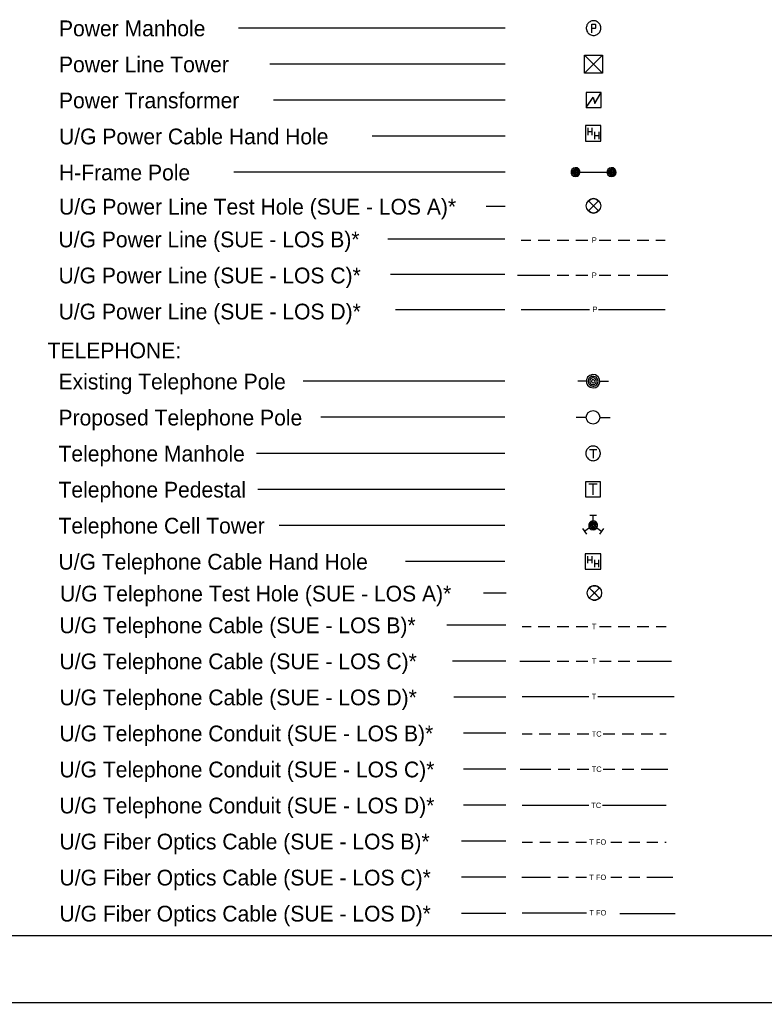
# Model space of a CAD drawing. Extents: x 0 to 3, y 0 to 1.83.
# Drawn here: x 1.443 to 2.138, y 0 to 0.917 of the extents above; entities that cross this region are included whole.
import ezdxf

# ---------------------------------------------------------------- set-up
doc = ezdxf.new("R2010")
doc.units = 0
for name, color, linetype in [('Prop DSN Text', 7, 'Continuous'), ('Scratch_Level_3', 7, 'Continuous'), ('Sheet_Plan', 7, 'Continuous'), ('Sheet_Symbology', 7, 'Continuous'), ('z - Construction', 7, 'Continuous')]:
    doc.layers.add(name, color=color, linetype=linetype)

msp = doc.modelspace()

# ---------------------------------------------------------------- linework, layer by layer
at = {"layer": 'Prop DSN Text'}
for points in [[(1.98436, 0.38682), (1.97486, 0.37732), (1.97961, 0.38207), (1.97486, 0.38682), (1.98436, 0.37732)], [(1.97486, 0.38682), (1.97961, 0.38207), (1.98436, 0.38682)], [(1.98436, 0.37732), (1.97961, 0.38207), (1.97486, 0.37732)]]:
    msp.add_lwpolyline(points, dxfattribs=at)
msp.add_circle((1.97961, 0.38207), 0.00672, dxfattribs=at)
for start, end in [(45, 135), (225, 315)]:
    msp.add_arc((1.97961, 0.38207), 0.00672, start, end, dxfattribs=at)
at = {"layer": 'Scratch_Level_3'}
for points in [[(1.98357, 0.74811), (1.97406, 0.7386), (1.97881, 0.74336), (1.97406, 0.74811), (1.98357, 0.7386)], [(1.97406, 0.74811), (1.97881, 0.74336), (1.98357, 0.74811)], [(1.98357, 0.7386), (1.97881, 0.74336), (1.97406, 0.7386)]]:
    msp.add_lwpolyline(points, dxfattribs=at)
msp.add_circle((1.97881, 0.74336), 0.00672, dxfattribs=at)
for start, end in [(45, 135), (225, 315)]:
    msp.add_arc((1.97881, 0.74336), 0.00672, start, end, dxfattribs=at)
at = {"layer": 'Sheet_Plan'}
msp.add_line((0.0625, 0.0625), (2.77079, 0.0625), dxfattribs=at)
at = {"layer": 'Sheet_Symbology'}
for p, q in [((1.89643, 0.90927), (1.6473, 0.90927)), ((1.98022, 0.90894), (1.97716, 0.90894)), ((1.98076, 0.91238), (1.98076, 0.90949)), ((1.98729, 0.88408), (1.9705, 0.86728)), ((1.98729, 0.86728), (1.9705, 0.88408)), ((1.89643, 0.87564), (1.67671, 0.87564)), ((1.89643, 0.84201), (1.68012, 0.84201)), ((1.89643, 0.80837), (1.77218, 0.80837)), ((1.97335, 0.8161), (1.97335, 0.80932)), ((1.97335, 0.81264), (1.97722, 0.81264)), ((1.97722, 0.8161), (1.97722, 0.80932)), ((1.97982, 0.8124), (1.97982, 0.80563)), ((1.97982, 0.80895), (1.98369, 0.80895)), ((1.98369, 0.8124), (1.98369, 0.80563)), ((1.89643, 0.77474), (1.64304, 0.77474)), ((1.96204, 0.77474), (1.99567, 0.77474)), ((1.89643, 0.74283), (1.87855, 0.74283)), ((1.89598, 0.71229), (1.78681, 0.71229)), ((1.91113, 0.71146), (1.92038, 0.71146)), ((1.92711, 0.71146), (1.93804, 0.71146)), ((1.94476, 0.71146), (1.95569, 0.71146)), ((1.96242, 0.71146), (1.97335, 0.71146)), ((1.98411, 0.71146), (1.99504, 0.71146)), ((2.00177, 0.71146), (2.0127, 0.71146)), ((2.01942, 0.71146), (2.03035, 0.71146)), ((2.03708, 0.71146), (2.04566, 0.71146)), ((1.89598, 0.6793), (1.7894, 0.6793)), ((1.90773, 0.67866), (1.93804, 0.67866)), ((1.94476, 0.67866), (1.95569, 0.67866)), ((1.96242, 0.67866), (1.97335, 0.67866)), ((1.98411, 0.67866), (1.99504, 0.67866)), ((2.00177, 0.67866), (2.0127, 0.67866)), ((2.01942, 0.67866), (2.04806, 0.67866)), ((1.89598, 0.64631), (1.79392, 0.64631)), ((1.91113, 0.64678), (1.97518, 0.64678)), ((1.98358, 0.64678), (2.04566, 0.64678)), ((1.89598, 0.57963), (1.70783, 0.57963)), ((1.97218, 0.57963), (1.96412, 0.57963)), ((1.9846, 0.57963), (1.99267, 0.57963)), ((1.89598, 0.546), (1.72435, 0.546)), ((1.97215, 0.54598), (1.96269, 0.54598)), ((1.98476, 0.54598), (1.99422, 0.54598)), ((1.98189, 0.51554), (1.97495, 0.51554)), ((1.97839, 0.51554), (1.97839, 0.50789)), ((1.89598, 0.51237), (1.66415, 0.51237)), ((1.89598, 0.47874), (1.66533, 0.47874)), ((1.97446, 0.48381), (1.98233, 0.48381)), ((1.97839, 0.47367), (1.97839, 0.48381)), ((1.97524, 0.45462), (1.98155, 0.45462)), ((1.97839, 0.44925), (1.97839, 0.45462)), ((1.89598, 0.44511), (1.6854, 0.44511)), ((1.97242, 0.43707), (1.9688, 0.44224)), ((1.97502, 0.44274), (1.97061, 0.43965)), ((1.98179, 0.44275), (1.98619, 0.43966)), ((1.988, 0.44224), (1.98438, 0.43708)), ((1.97324, 0.41656), (1.97324, 0.40979)), ((1.97324, 0.41311), (1.97711, 0.41311)), ((1.97711, 0.41656), (1.97711, 0.40979)), ((1.97971, 0.41287), (1.97971, 0.4061)), ((1.98358, 0.41287), (1.98358, 0.4061)), ((1.89598, 0.41148), (1.80343, 0.41148)), ((1.97971, 0.40942), (1.98358, 0.40942)), ((1.89735, 0.38175), (1.87607, 0.38175)), ((1.89689, 0.35212), (1.84177, 0.35212)), ((1.91205, 0.35078), (1.9205, 0.35078)), ((1.92723, 0.35078), (1.93816, 0.35078)), ((1.94488, 0.35078), (1.95581, 0.35078)), ((1.96254, 0.35078), (1.97347, 0.35078)), ((1.98423, 0.35078), (1.99516, 0.35078)), ((2.00189, 0.35078), (2.01282, 0.35078)), ((2.01954, 0.35078), (2.03047, 0.35078)), ((2.0372, 0.35078), (2.04657, 0.35078)), ((1.89689, 0.31849), (1.84708, 0.31849)), ((1.90995, 0.31849), (1.93816, 0.31849)), ((1.94488, 0.31849), (1.95581, 0.31849)), ((1.96254, 0.31849), (1.97347, 0.31849)), ((1.98423, 0.31849), (1.99516, 0.31849)), ((2.00189, 0.31849), (2.01282, 0.31849)), ((2.01954, 0.31849), (2.05156, 0.31849)), ((1.89689, 0.28486), (1.84837, 0.28486)), ((1.91205, 0.28545), (1.97448, 0.28545)), ((1.98288, 0.28545), (2.05415, 0.28545)), ((1.89689, 0.25123), (1.85744, 0.25123)), ((1.91205, 0.25051), (1.92144, 0.25051)), ((1.92817, 0.25051), (1.9391, 0.25051)), ((1.94583, 0.25051), (1.95676, 0.25051)), ((1.96348, 0.25051), (1.97441, 0.25051)), ((1.98787, 0.25051), (1.9988, 0.25051)), ((2.00552, 0.25051), (2.01645, 0.25051)), ((2.02318, 0.25051), (2.03411, 0.25051)), ((2.04084, 0.25051), (2.04657, 0.25051)), ((1.89689, 0.21759), (1.85744, 0.21759)), ((1.91045, 0.21759), (1.9391, 0.21759)), ((1.94583, 0.21759), (1.95676, 0.21759)), ((1.96348, 0.21759), (1.97441, 0.21759)), ((1.98787, 0.21759), (1.9988, 0.21759)), ((2.00552, 0.21759), (2.01645, 0.21759)), ((2.02318, 0.21759), (2.04819, 0.21759)), ((1.89689, 0.18396), (1.85744, 0.18396)), ((1.91205, 0.18388), (1.97441, 0.18388)), ((1.98703, 0.18388), (2.04657, 0.18388)), ((1.89689, 0.15033), (1.85549, 0.15033)), ((1.91205, 0.1496), (1.92187, 0.1496)), ((1.92859, 0.1496), (1.93868, 0.1496)), ((1.94541, 0.1496), (1.9555, 0.1496)), ((1.96222, 0.1496), (1.97231, 0.1496)), ((1.99501, 0.1496), (2.0051, 0.1496)), ((2.01183, 0.1496), (2.02192, 0.1496)), ((2.02864, 0.1496), (2.03873, 0.1496)), ((2.04546, 0.1496), (2.04657, 0.1496)), ((1.89689, 0.1167), (1.85549, 0.1167)), ((1.91174, 0.1167), (1.93868, 0.1167)), ((1.94541, 0.1167), (1.9555, 0.1167)), ((1.96222, 0.1167), (1.97231, 0.1167)), ((1.99501, 0.1167), (2.0051, 0.1167)), ((2.01183, 0.1167), (2.02192, 0.1167)), ((2.02864, 0.1167), (2.05271, 0.1167)), ((1.89689, 0.08307), (1.85549, 0.08307)), ((1.91205, 0.08362), (1.97238, 0.08362)), ((2.00348, 0.08298), (2.05498, 0.08298))]:
    msp.add_line(p, q, dxfattribs=at)
for points in [[(1.97885, 0.91609), (1.97798, 0.91604), (1.97716, 0.91588), (1.97634, 0.9156), (1.97558, 0.91522), (1.97487, 0.91478), (1.97421, 0.91424), (1.97361, 0.91358), (1.97312, 0.91293), (1.97268, 0.91216), (1.97241, 0.91134), (1.97219, 0.91052), (1.97208, 0.90971), (1.97208, 0.90883), (1.97219, 0.90801), (1.97241, 0.90714), (1.97268, 0.90637), (1.97312, 0.90561), (1.97361, 0.90495), (1.97421, 0.9043), (1.97487, 0.90375), (1.97558, 0.90332), (1.97634, 0.90293), (1.97716, 0.90266), (1.97803, 0.9025), (1.97885, 0.90244), (1.97973, 0.9025), (1.98054, 0.90266), (1.98137, 0.90293), (1.98213, 0.90332), (1.98284, 0.90375), (1.98349, 0.9043), (1.9841, 0.90495), (1.98459, 0.90561), (1.98503, 0.90637), (1.9853, 0.90719), (1.98552, 0.90801), (1.98562, 0.90883), (1.98562, 0.90971), (1.98552, 0.91052), (1.9853, 0.9114), (1.98503, 0.91216), (1.98459, 0.91293), (1.9841, 0.91358), (1.98349, 0.91424), (1.98284, 0.91478), (1.98213, 0.91522), (1.98137, 0.9156), (1.98054, 0.91588), (1.97967, 0.91604), (1.97885, 0.91609)], [(1.97716, 0.9049), (1.97716, 0.90894), (1.97716, 0.91293), (1.98022, 0.91293)], [(1.98022, 0.91293), (1.98044, 0.91287), (1.9806, 0.91276), (1.98071, 0.9126), (1.98076, 0.91238)], [(1.98076, 0.90949), (1.98071, 0.90927), (1.9806, 0.9091), (1.98044, 0.909), (1.98022, 0.90894)], [(1.98729, 0.86728), (1.9705, 0.86728), (1.9705, 0.88408), (1.98729, 0.88408), (1.98729, 0.86728), (1.9705, 0.86728), (1.9705, 0.88408), (1.98729, 0.88408), (1.98729, 0.86728)], [(1.97184, 0.835), (1.97846, 0.84451), (1.98007, 0.83934), (1.98586, 0.84901)], [(1.97184, 0.835), (1.97852, 0.8449), (1.98002, 0.83895), (1.98586, 0.84901)], [(1.97184, 0.835), (1.98586, 0.835), (1.98586, 0.84901), (1.97184, 0.84901), (1.97184, 0.835)], [(1.97126, 0.80377), (1.98574, 0.80377), (1.98574, 0.81825), (1.97126, 0.81825), (1.97126, 0.80377)], [(1.9651, 0.77474), (1.96502, 0.77549), (1.96477, 0.77615), (1.96435, 0.77673), (1.96386, 0.77722), (1.96328, 0.77756), (1.96253, 0.77772), (1.96187, 0.77781), (1.96113, 0.77764), (1.96046, 0.77739), (1.95997, 0.77698), (1.95947, 0.7764), (1.95914, 0.77582), (1.95897, 0.77507), (1.95897, 0.77441), (1.95914, 0.77367), (1.95947, 0.77309), (1.95997, 0.77251), (1.96046, 0.7721), (1.96113, 0.77185), (1.96187, 0.77168), (1.96253, 0.77176), (1.96328, 0.77193), (1.96386, 0.77226), (1.96435, 0.77276), (1.96477, 0.77334), (1.96502, 0.774), (1.9651, 0.77474)], [(1.9641, 0.77474), (1.96402, 0.77532), (1.96377, 0.7759), (1.96336, 0.77632), (1.96287, 0.77665), (1.96237, 0.77681), (1.96171, 0.77681), (1.96121, 0.77665), (1.96071, 0.77632), (1.9603, 0.7759), (1.96005, 0.77532), (1.95997, 0.77474), (1.96005, 0.77416), (1.9603, 0.77359), (1.96071, 0.77317), (1.96121, 0.77284), (1.96171, 0.77268), (1.96237, 0.77268), (1.96287, 0.77284), (1.96336, 0.77317), (1.96377, 0.77359), (1.96402, 0.77416), (1.9641, 0.77474)], [(1.96303, 0.77474), (1.96295, 0.77516), (1.9627, 0.77549), (1.96237, 0.77565), (1.96195, 0.77574), (1.96154, 0.77557), (1.96121, 0.77532), (1.96104, 0.77491), (1.96104, 0.77458), (1.96121, 0.77416), (1.96154, 0.77391), (1.96195, 0.77375), (1.96237, 0.77383), (1.9627, 0.774), (1.96295, 0.77433), (1.96303, 0.77474)], [(1.99873, 0.77474), (1.99865, 0.77549), (1.9984, 0.77615), (1.99798, 0.77673), (1.99749, 0.77722), (1.99691, 0.77756), (1.99616, 0.77772), (1.9955, 0.77781), (1.99476, 0.77764), (1.9941, 0.77739), (1.9936, 0.77698), (1.9931, 0.7764), (1.99277, 0.77582), (1.9926, 0.77507), (1.9926, 0.77441), (1.99277, 0.77367), (1.9931, 0.77309), (1.9936, 0.77251), (1.9941, 0.7721), (1.99476, 0.77185), (1.9955, 0.77168), (1.99616, 0.77176), (1.99691, 0.77193), (1.99749, 0.77226), (1.99798, 0.77276), (1.9984, 0.77334), (1.99865, 0.774), (1.99873, 0.77474)], [(1.99774, 0.77474), (1.99765, 0.77532), (1.99741, 0.7759), (1.99699, 0.77632), (1.9965, 0.77665), (1.996, 0.77681), (1.99534, 0.77681), (1.99484, 0.77665), (1.99434, 0.77632), (1.99393, 0.7759), (1.99368, 0.77532), (1.9936, 0.77474), (1.99368, 0.77416), (1.99393, 0.77359), (1.99434, 0.77317), (1.99484, 0.77284), (1.99534, 0.77268), (1.996, 0.77268), (1.9965, 0.77284), (1.99699, 0.77317), (1.99741, 0.77359), (1.99765, 0.77416), (1.99774, 0.77474)], [(1.99666, 0.77474), (1.99658, 0.77516), (1.99633, 0.77549), (1.996, 0.77565), (1.99559, 0.77574), (1.99517, 0.77557), (1.99484, 0.77532), (1.99467, 0.77491), (1.99467, 0.77458), (1.99484, 0.77416), (1.99517, 0.77391), (1.99559, 0.77375), (1.996, 0.77383), (1.99633, 0.774), (1.99658, 0.77433), (1.99666, 0.77474)], [(1.98299, 0.57963), (1.98286, 0.58075), (1.98249, 0.58174), (1.98187, 0.58261), (1.98112, 0.58335), (1.98026, 0.58385), (1.97914, 0.5841), (1.97814, 0.58423), (1.97703, 0.58398), (1.97603, 0.5836), (1.97529, 0.58298), (1.97455, 0.58211), (1.97405, 0.58124), (1.9738, 0.58013), (1.9738, 0.57914), (1.97405, 0.57802), (1.97455, 0.57715), (1.97529, 0.57628), (1.97603, 0.57566), (1.97703, 0.57529), (1.97814, 0.57504), (1.97914, 0.57516), (1.98026, 0.57541), (1.98112, 0.57591), (1.98187, 0.57665), (1.98249, 0.57752), (1.98286, 0.57852), (1.98299, 0.57963)], [(1.9815, 0.57963), (1.98137, 0.5805), (1.981, 0.58137), (1.98038, 0.58199), (1.97964, 0.58249), (1.97889, 0.58273), (1.9779, 0.58273), (1.97715, 0.58249), (1.97641, 0.58199), (1.97579, 0.58137), (1.97541, 0.5805), (1.97529, 0.57963), (1.97541, 0.57876), (1.97579, 0.5779), (1.97641, 0.57727), (1.97715, 0.57678), (1.9779, 0.57653), (1.97889, 0.57653), (1.97964, 0.57678), (1.98038, 0.57727), (1.981, 0.5779), (1.98137, 0.57876), (1.9815, 0.57963)], [(1.97988, 0.57963), (1.97976, 0.58025), (1.97939, 0.58075), (1.97889, 0.581), (1.97827, 0.58112), (1.97765, 0.58088), (1.97715, 0.5805), (1.9769, 0.57988), (1.9769, 0.57938), (1.97715, 0.57876), (1.97765, 0.57839), (1.97827, 0.57814), (1.97889, 0.57827), (1.97939, 0.57852), (1.97976, 0.57901), (1.97988, 0.57963)], [(1.97839, 0.5192), (1.97752, 0.51914), (1.9767, 0.51898), (1.97588, 0.5187), (1.97512, 0.51832), (1.97441, 0.51789), (1.97375, 0.51734), (1.97315, 0.51668), (1.97266, 0.51603), (1.97222, 0.51527), (1.97195, 0.51445), (1.97173, 0.51363), (1.97162, 0.51281), (1.97162, 0.51193), (1.97173, 0.51111), (1.97195, 0.51024), (1.97222, 0.50947), (1.97266, 0.50871), (1.97315, 0.50805), (1.97375, 0.5074), (1.97441, 0.50685), (1.97512, 0.50642), (1.97588, 0.50603), (1.9767, 0.50576), (1.97757, 0.5056), (1.97839, 0.50554), (1.97927, 0.5056), (1.98008, 0.50576), (1.98091, 0.50603), (1.98167, 0.50642), (1.98238, 0.50685), (1.98303, 0.5074), (1.98364, 0.50805), (1.98413, 0.50871), (1.98457, 0.50947), (1.98484, 0.51029), (1.98506, 0.51111), (1.98517, 0.51193), (1.98517, 0.51281), (1.98506, 0.51363), (1.98484, 0.5145), (1.98457, 0.51527), (1.98413, 0.51603), (1.98364, 0.51668), (1.98303, 0.51734), (1.98238, 0.51789), (1.98167, 0.51832), (1.98091, 0.5187), (1.98008, 0.51898), (1.97921, 0.51914), (1.97839, 0.5192)], [(1.97132, 0.47166), (1.98547, 0.47166), (1.98547, 0.48582), (1.97132, 0.48582), (1.97132, 0.47166)], [(1.98146, 0.44511), (1.98137, 0.44585), (1.98112, 0.44651), (1.98071, 0.44709), (1.98021, 0.44759), (1.97963, 0.44792), (1.97889, 0.44809), (1.97823, 0.44817), (1.97748, 0.448), (1.97682, 0.44775), (1.97633, 0.44734), (1.97583, 0.44676), (1.9755, 0.44618), (1.97533, 0.44544), (1.97533, 0.44478), (1.9755, 0.44403), (1.97583, 0.44345), (1.97633, 0.44287), (1.97682, 0.44246), (1.97748, 0.44221), (1.97823, 0.44204), (1.97889, 0.44213), (1.97963, 0.44229), (1.98021, 0.44263), (1.98071, 0.44312), (1.98112, 0.4437), (1.98137, 0.44436), (1.98146, 0.44511)], [(1.98046, 0.44511), (1.98038, 0.44569), (1.98013, 0.44626), (1.97972, 0.44668), (1.97922, 0.44701), (1.97872, 0.44718), (1.97806, 0.44718), (1.97756, 0.44701), (1.97707, 0.44668), (1.97666, 0.44626), (1.97641, 0.44569), (1.97633, 0.44511), (1.97641, 0.44453), (1.97666, 0.44395), (1.97707, 0.44353), (1.97756, 0.4432), (1.97806, 0.44304), (1.97872, 0.44304), (1.97922, 0.4432), (1.97972, 0.44353), (1.98013, 0.44395), (1.98038, 0.44453), (1.98046, 0.44511)], [(1.97939, 0.44511), (1.9793, 0.44552), (1.97906, 0.44585), (1.97872, 0.44602), (1.97831, 0.4461), (1.9779, 0.44594), (1.97756, 0.44569), (1.9774, 0.44527), (1.9774, 0.44494), (1.97756, 0.44453), (1.9779, 0.44428), (1.97831, 0.44411), (1.97872, 0.4442), (1.97906, 0.44436), (1.9793, 0.44469), (1.97939, 0.44511)], [(1.97115, 0.40424), (1.98563, 0.40424), (1.98563, 0.41871), (1.97115, 0.41871), (1.97115, 0.40424)]]:
    msp.add_lwpolyline(points, dxfattribs=at)
for points in [[(1.96204, 0.7706), (1.96377, 0.77094), (1.96493, 0.77176), (1.96584, 0.77292), (1.96618, 0.77449), (1.96601, 0.77599), (1.96518, 0.77747), (1.96353, 0.77872), (1.96162, 0.77888), (1.95997, 0.77838), (1.95864, 0.77722), (1.95798, 0.77565), (1.95798, 0.77383), (1.95864, 0.77226), (1.96013, 0.77102)], [(1.99567, 0.7706), (1.99741, 0.77094), (1.99856, 0.77176), (1.99948, 0.77292), (1.99981, 0.77449), (1.99964, 0.77599), (1.99881, 0.77747), (1.99716, 0.77872), (1.99525, 0.77888), (1.9936, 0.77838), (1.99228, 0.77722), (1.99161, 0.77565), (1.99161, 0.77383), (1.99228, 0.77226), (1.99376, 0.77102)], [(1.97839, 0.57342), (1.981, 0.57392), (1.98274, 0.57516), (1.9841, 0.5769), (1.9846, 0.57926), (1.98435, 0.58149), (1.98311, 0.58373), (1.98063, 0.58559), (1.97777, 0.58584), (1.97529, 0.58509), (1.9733, 0.58335), (1.97231, 0.581), (1.97231, 0.57827), (1.9733, 0.57591), (1.97554, 0.57404)], [(1.97839, 0.44097), (1.98013, 0.4413), (1.98129, 0.44213), (1.9822, 0.44329), (1.98253, 0.44486), (1.98237, 0.44635), (1.98154, 0.44784), (1.97988, 0.44908), (1.97798, 0.44925), (1.97633, 0.44875), (1.975, 0.44759), (1.97434, 0.44602), (1.97434, 0.4442), (1.975, 0.44263), (1.97649, 0.44138)]]:
    msp.add_lwpolyline(points, close=True, dxfattribs=at)
msp.add_circle((1.97839, 0.546), 0.00631, dxfattribs=at)
at = {"layer": 'z - Construction'}
msp.add_line((0, 0), (2.83333, 0), dxfattribs=at)

# ---------------------------------------------------------------- texts
at = {"layer": 'Sheet_Symbology'}
for s, height, p in [('Power Manhole', 0.0147137, (1.47987, 0.90164)), ('Power Line Tower', 0.0147137, (1.47987, 0.86803)), ('Power Transformer', 0.0147137, (1.47985, 0.8344)), ('U/G Power Cable Hand Hole', 0.0147137, (1.47989, 0.80074)), ('H-Frame Pole', 0.0147137, (1.47989, 0.76711)), ('U/G Power Line Test Hole (SUE - LOS A)*', 0.0147137, (1.47989, 0.7352)), ('U/G Power Line (SUE - LOS B)*', 0.0147137, (1.47943, 0.70466)), ('P', 0.00504, (1.97722, 0.70894)), ('U/G Power Line (SUE - LOS C)*', 0.0147137, (1.47947, 0.671)), ('P', 0.00504, (1.97722, 0.67613)), ('U/G Power Line (SUE - LOS D)*', 0.0147137, (1.47952, 0.63735)), ('P', 0.00504, (1.97787, 0.64425)), ('TELEPHONE:', 0.014714, (1.46924, 0.60108)), ('Existing Telephone Pole', 0.0147137, (1.47943, 0.572)), ('Proposed Telephone Pole', 0.0147137, (1.47943, 0.53837)), ('Telephone Manhole', 0.0147137, (1.47943, 0.50474)), ('Telephone Pedestal', 0.0147137, (1.47943, 0.47111)), ('Telephone Cell Tower', 0.0147137, (1.47945, 0.43748)), ('U/G Telephone Cable Hand Hole', 0.0147137, (1.47945, 0.40385)), ('U/G Telephone Test Hole (SUE - LOS A)*', 0.0147137, (1.48083, 0.37412)), ('U/G Telephone Cable (SUE - LOS B)*', 0.0147137, (1.48037, 0.34449)), ('T', 0.00504, (1.97725, 0.34825)), ('U/G Telephone Cable (SUE - LOS C)*', 0.0147137, (1.48037, 0.31086)), ('T', 0.00504, (1.97725, 0.31597)), ('U/G Telephone Cable (SUE - LOS D)*', 0.0147137, (1.48037, 0.27723)), ('T', 0.00504, (1.97708, 0.28292)), ('U/G Telephone Conduit (SUE - LOS B)*', 0.0147137, (1.48037, 0.2436)), ('TC', 0.005045, (1.9771, 0.24798)), ('U/G Telephone Conduit (SUE - LOS C)*', 0.0147137, (1.48037, 0.20996)), ('TC', 0.005045, (1.9771, 0.21507)), ('U/G Telephone Conduit (SUE - LOS D)*', 0.0147137, (1.48037, 0.17633)), ('TC', 0.005045, (1.97668, 0.18136)), ('U/G Fiber Optics Cable (SUE - LOS B)*', 0.0147137, (1.48037, 0.1427)), ('T FO', 0.005045, (1.97483, 0.14708)), ('U/G Fiber Optics Cable (SUE - LOS C)*', 0.0147137, (1.48037, 0.10907)), ('T FO', 0.005045, (1.97483, 0.11418)), ('U/G Fiber Optics Cable (SUE - LOS D)*', 0.0147137, (1.48037, 0.07544)), ('T FO', 0.005045, (1.9749, 0.0811))]:
    msp.add_text(s, height=height, dxfattribs=at).set_placement(p)

doc.saveas('drawing.dxf')
